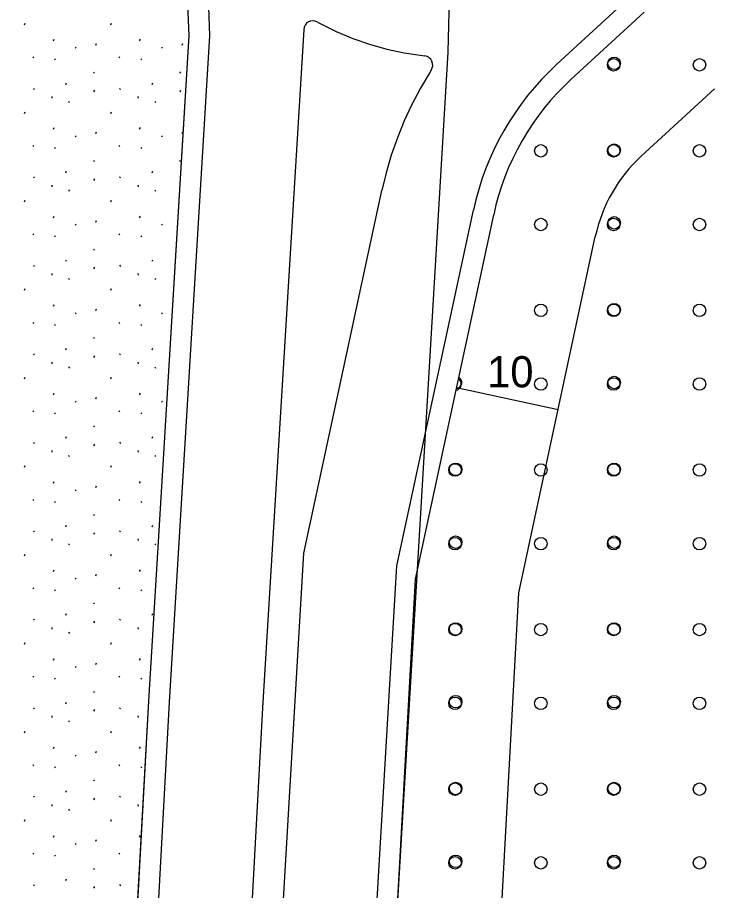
# Model space of a CAD drawing. Extents: x 419396 to 421519, y 4453567 to 4456767.
# Drawn here: x 420874 to 420941, y 4455563.3 to 4455647.3 of the extents above; entities that cross this region are included whole.
import ezdxf

# ---------------------------------------------------------------- set-up
doc = ezdxf.new("R2010")
doc.units = 0
for name, color, linetype in [('0_KADASTRO', 7, 'Continuous'), ('ADAKENARI1000', 7, 'Continuous'), ('F_YAPI_YAKLAŞMA', 7, 'Continuous'), ('KALDIRIM', 7, 'Continuous'), ('Level 33', 7, 'Continuous'), ('Level 41', 7, 'Continuous')]:
    doc.layers.add(name, color=color, linetype=linetype)

msp = doc.modelspace()

# ---------------------------------------------------------------- linework, layer by layer
at = {"layer": '0_KADASTRO'}
msp.add_lwpolyline([(420545.417, 4455447.038), (420561.035, 4455696.592), (420608.268, 4455685.53), (420614.844, 4455734.095), (420621.113, 4455745.073), (420621.38, 4455786.205), (420636.291, 4455823.285), (420701.58, 4455861.23), (420708.62, 4455863.92), (420715.79, 4455864.57), (420723.78, 4455862.78), (420730.13, 4455859.19), (420735, 4455853.4), (420771.9, 4455797.51), (420787.06, 4455778.4), (420884.04, 4455668.02), (420888.93, 4455658.72), (420890.16, 4455653.06), (420890.461, 4455645.521), (420886.579, 4455581.517), (420884.979, 4455552.191), (420718.56, 4455563.04), (420710.4, 4455437.34), (420549.3, 4455446.81)], close=True, dxfattribs=at)
msp.add_lwpolyline([(420889.849, 4455182.58), (420910.449, 4455560.119), (420915.412, 4455643.953), (420915.577, 4455650.455), (420914.598, 4455657.957), (420913.457, 4455663.665), (420911.337, 4455669.862), (420909.752, 4455673.126), (420911.566, 4455679.673), (420935.859, 4455688.268), (420947.761, 4455688.766), (420960.081, 4455684.751), (420973.092, 4455678.471), (421003.122, 4455663.97), (421028.474, 4455648.453), (421040.228, 4455638.432), (421137.175, 4455559.091), (421140.509, 4455550.953), (421136.038, 4455509.502), (421128.218, 4455437.471), (421062.987, 4455307.75)], dxfattribs=at)
at = {"layer": 'ADAKENARI1000'}
for p, q in [((420890.16, 4455653.06), (420890.46, 4455645.54)), ((420927.217, 4455641.299), (420934.264, 4455647.783)), ((420890.46, 4455645.54), (420886.579, 4455581.517)), ((420912.257, 4455593.26), (420919.791, 4455628.308)), ((420899.408, 4455357.777), (420912.257, 4455593.26)), ((420886.579, 4455581.517), (420884.979, 4455552.191))]:
    msp.add_line(p, q, dxfattribs=at)
msp.add_arc((420943.952, 4455623.115), 24.712, 132.62198, 167.86854, dxfattribs=at)
at = {"layer": 'F_YAPI_YAKLAŞMA'}
for p, q in [((420933.989, 4455633.941), (420941.035, 4455640.425)), ((420922.2, 4455591.928), (420929.568, 4455626.206)), ((420925.987, 4455609.549), (420916.211, 4455611.651)), ((420909.394, 4455357.232), (420922.2, 4455591.928))]:
    msp.add_line(p, q, dxfattribs=at)
msp.add_arc((420943.952, 4455623.115), 14.712, 132.62198, 167.86854, dxfattribs=at)
at = {"layer": 'KALDIRIM'}
for p, q in [((420892.153, 4455653.269), (420892.462, 4455645.519)), ((420925.863, 4455642.771), (420932.91, 4455649.255)), ((420901.516, 4455646.126), (420897.561, 4455580.885)), ((420902.836, 4455646.84), (420903.096, 4455646.691)), ((420903.096, 4455646.691), (420904.64, 4455645.931)), ((420892.462, 4455645.519), (420888.576, 4455581.402)), ((420904.64, 4455645.931), (420906.228, 4455645.268)), ((420906.228, 4455645.268), (420907.854, 4455644.704)), ((420907.854, 4455644.704), (420909.511, 4455644.241)), ((420909.511, 4455644.241), (420911.194, 4455643.88)), ((420911.194, 4455643.88), (420913.182, 4455643.58)), ((420913.641, 4455641.999), (420912.746, 4455640.481)), ((420913.788, 4455642.222), (420913.641, 4455641.999)), ((420912.746, 4455640.481), (420911.927, 4455638.92)), ((420911.927, 4455638.92), (420911.187, 4455637.321)), ((420911.187, 4455637.321), (420910.526, 4455635.688)), ((420910.526, 4455635.688), (420909.946, 4455634.024)), ((420909.946, 4455634.024), (420909.449, 4455632.333)), ((420909.449, 4455632.333), (420909.037, 4455630.62)), ((420901.538, 4455595.736), (420909.037, 4455630.62)), ((420910.482, 4455594.517), (420917.836, 4455628.728)), ((420899.467, 4455560.744), (420901.538, 4455595.736)), ((420908.452, 4455560.233), (420910.482, 4455594.517)), ((420888.576, 4455581.402), (420886.976, 4455552.082)), ((420897.561, 4455580.885), (420895.963, 4455551.592))]:
    msp.add_line(p, q, dxfattribs=at)
for centre, radius, start, end in [((420902.398, 4455646.072), 0.884, 60.28995, 176.53104), ((420913.05, 4455642.707), 0.882, 326.66214, 81.42048), ((420943.952, 4455623.115), 26.712, 132.62198, 167.86854)]:
    msp.add_arc(centre, radius, start, end, dxfattribs=at)
at = {"layer": 'Level 33'}
for centre in [(420931.332, 4455642.719), (420931.387, 4455642.87), (420939.589, 4455642.719), (420924.332, 4455634.455), (420931.332, 4455634.455), (420931.387, 4455634.518), (420939.589, 4455634.455), (420924.332, 4455627.367), (420931.332, 4455627.367), (420931.387, 4455627.518), (420939.589, 4455627.367), (420924.332, 4455619.103), (420931.332, 4455619.103), (420931.387, 4455619.166), (420939.589, 4455619.103), (420924.332, 4455612.015), (420931.332, 4455612.015), (420931.387, 4455612.166), (420939.589, 4455612.015), (420916.075, 4455603.751), (420916.13, 4455603.814), (420924.332, 4455603.751), (420931.332, 4455603.751), (420931.387, 4455603.814), (420939.589, 4455603.751), (420916.13, 4455596.814), (420931.387, 4455596.814), (420916.075, 4455596.663), (420924.332, 4455596.663), (420931.332, 4455596.663), (420939.589, 4455596.663), (420916.075, 4455588.399), (420916.13, 4455588.462), (420924.332, 4455588.399), (420931.332, 4455588.399), (420931.387, 4455588.462), (420939.589, 4455588.399), (420916.075, 4455581.311), (420916.13, 4455581.462), (420924.332, 4455581.311), (420931.332, 4455581.311), (420931.387, 4455581.462), (420939.589, 4455581.311), (420916.075, 4455573.047), (420916.13, 4455573.11), (420924.332, 4455573.047), (420931.332, 4455573.047), (420931.387, 4455573.11), (420939.589, 4455573.047), (420916.075, 4455565.959), (420916.13, 4455566.11), (420924.332, 4455565.959), (420931.332, 4455565.959), (420931.387, 4455566.11), (420939.589, 4455565.959)]:
    msp.add_circle(centre, 0.6, dxfattribs=at)
for centre, start, end in [((420916.075, 4455612.015), 278.29903, 57.43805), ((420916.13, 4455612.166), 276.0035, 59.73359)]:
    msp.add_arc(centre, 0.6, start, end, dxfattribs=at)
at = {"layer": 'Level 41'}
for p, q in [((420874.669, 4455646.561), (420874.741, 4455646.721)), ((420882.962, 4455646.561), (420883.034, 4455646.721)), ((420877.441, 4455645.031), (420877.511, 4455645.191)), ((420879.536, 4455644.415), (420879.607, 4455644.309)), ((420881.524, 4455644.623), (420881.595, 4455644.783)), ((420885.734, 4455645.031), (420885.804, 4455645.191)), ((420887.829, 4455644.415), (420887.9, 4455644.309)), ((420889.817, 4455644.623), (420889.888, 4455644.783)), ((420875.451, 4455643.486), (420875.522, 4455643.379)), ((420877.55, 4455643.294), (420877.621, 4455643.187)), ((420883.744, 4455643.486), (420883.815, 4455643.379)), ((420885.843, 4455643.294), (420885.914, 4455643.187)), ((420881.288, 4455642.033), (420881.359, 4455641.926)), ((420889.581, 4455642.033), (420889.652, 4455641.926)), ((420875.518, 4455640.456), (420875.589, 4455640.349)), ((420878.647, 4455640.84), (420878.718, 4455640.999)), ((420881.346, 4455640.111), (420881.418, 4455640.271)), ((420883.811, 4455640.456), (420883.882, 4455640.349)), ((420886.94, 4455640.84), (420887.011, 4455640.999)), ((420889.639, 4455640.111), (420889.711, 4455640.271)), ((420877.276, 4455639.665), (420877.294, 4455639.505)), ((420885.569, 4455639.665), (420885.587, 4455639.505)), ((420878.906, 4455639.195), (420878.976, 4455639.088)), ((420887.199, 4455639.195), (420887.269, 4455639.088)), ((420874.669, 4455638.051), (420874.741, 4455638.211)), ((420882.962, 4455638.051), (420883.034, 4455638.211)), ((420877.441, 4455636.521), (420877.511, 4455636.681)), ((420881.524, 4455636.113), (420881.595, 4455636.273)), ((420885.734, 4455636.521), (420885.804, 4455636.681)), ((420889.817, 4455636.113), (420889.888, 4455636.273)), ((420879.536, 4455635.905), (420879.607, 4455635.799)), ((420887.829, 4455635.905), (420887.9, 4455635.799)), ((420875.451, 4455634.976), (420875.522, 4455634.869)), ((420877.55, 4455634.784), (420877.621, 4455634.677)), ((420883.744, 4455634.976), (420883.815, 4455634.869)), ((420885.843, 4455634.784), (420885.914, 4455634.677)), ((420881.288, 4455633.523), (420881.359, 4455633.416)), ((420889.581, 4455633.523), (420889.652, 4455633.416)), ((420875.518, 4455631.946), (420875.589, 4455631.839)), ((420878.647, 4455632.33), (420878.718, 4455632.489)), ((420883.811, 4455631.946), (420883.882, 4455631.839)), ((420886.94, 4455632.33), (420887.011, 4455632.489)), ((420877.276, 4455631.155), (420877.294, 4455630.995)), ((420881.346, 4455631.601), (420881.418, 4455631.761)), ((420885.569, 4455631.155), (420885.587, 4455630.995)), ((420878.906, 4455630.685), (420878.976, 4455630.578)), ((420887.199, 4455630.685), (420887.269, 4455630.578)), ((420874.669, 4455629.541), (420874.741, 4455629.701)), ((420882.962, 4455629.541), (420883.034, 4455629.701)), ((420877.441, 4455628.011), (420877.511, 4455628.171)), ((420881.524, 4455627.603), (420881.595, 4455627.763)), ((420885.734, 4455628.011), (420885.804, 4455628.171)), ((420879.536, 4455627.395), (420879.607, 4455627.289)), ((420887.829, 4455627.395), (420887.9, 4455627.289)), ((420875.451, 4455626.466), (420875.522, 4455626.359)), ((420877.55, 4455626.274), (420877.621, 4455626.167)), ((420883.744, 4455626.466), (420883.815, 4455626.359)), ((420885.843, 4455626.274), (420885.914, 4455626.167)), ((420881.288, 4455625.013), (420881.359, 4455624.906)), ((420875.518, 4455623.436), (420875.589, 4455623.329)), ((420878.647, 4455623.82), (420878.718, 4455623.979)), ((420883.811, 4455623.436), (420883.882, 4455623.329)), ((420886.94, 4455623.82), (420887.011, 4455623.979)), ((420877.276, 4455622.645), (420877.294, 4455622.485)), ((420881.346, 4455623.091), (420881.418, 4455623.251)), ((420885.569, 4455622.645), (420885.587, 4455622.485)), ((420878.906, 4455622.175), (420878.976, 4455622.068)), ((420887.199, 4455622.175), (420887.269, 4455622.068)), ((420874.669, 4455621.031), (420874.741, 4455621.191)), ((420882.962, 4455621.031), (420883.034, 4455621.191)), ((420877.441, 4455619.501), (420877.511, 4455619.661)), ((420881.524, 4455619.093), (420881.595, 4455619.253)), ((420885.734, 4455619.501), (420885.804, 4455619.661)), ((420879.536, 4455618.885), (420879.607, 4455618.779)), ((420887.829, 4455618.885), (420887.9, 4455618.779)), ((420875.451, 4455617.956), (420875.522, 4455617.849)), ((420877.55, 4455617.764), (420877.621, 4455617.657)), ((420883.744, 4455617.956), (420883.815, 4455617.849)), ((420885.843, 4455617.764), (420885.914, 4455617.657)), ((420881.288, 4455616.503), (420881.359, 4455616.396)), ((420878.647, 4455615.31), (420878.718, 4455615.469)), ((420886.94, 4455615.31), (420887.011, 4455615.469)), ((420875.518, 4455614.926), (420875.589, 4455614.819)), ((420881.346, 4455614.581), (420881.418, 4455614.741)), ((420883.811, 4455614.926), (420883.882, 4455614.819)), ((420877.276, 4455614.135), (420877.294, 4455613.975)), ((420878.906, 4455613.665), (420878.976, 4455613.558)), ((420885.569, 4455614.135), (420885.587, 4455613.975)), ((420887.199, 4455613.665), (420887.269, 4455613.558)), ((420874.669, 4455612.521), (420874.741, 4455612.681)), ((420882.962, 4455612.521), (420883.034, 4455612.681)), ((420877.441, 4455610.991), (420877.511, 4455611.151)), ((420885.734, 4455610.991), (420885.804, 4455611.151)), ((420879.536, 4455610.375), (420879.607, 4455610.269)), ((420881.524, 4455610.583), (420881.595, 4455610.743)), ((420887.829, 4455610.375), (420887.9, 4455610.269)), ((420875.451, 4455609.446), (420875.522, 4455609.339)), ((420877.55, 4455609.254), (420877.621, 4455609.147)), ((420883.744, 4455609.446), (420883.815, 4455609.339)), ((420885.843, 4455609.254), (420885.914, 4455609.147)), ((420881.288, 4455607.993), (420881.359, 4455607.886)), ((420878.647, 4455606.8), (420878.718, 4455606.959)), ((420886.94, 4455606.8), (420887.011, 4455606.959)), ((420875.518, 4455606.416), (420875.589, 4455606.309)), ((420881.346, 4455606.071), (420881.418, 4455606.231)), ((420883.811, 4455606.416), (420883.882, 4455606.309)), ((420877.276, 4455605.625), (420877.294, 4455605.465)), ((420878.906, 4455605.155), (420878.976, 4455605.048)), ((420885.569, 4455605.625), (420885.587, 4455605.465)), ((420887.199, 4455605.155), (420887.269, 4455605.048)), ((420874.669, 4455604.011), (420874.741, 4455604.171)), ((420882.962, 4455604.011), (420883.034, 4455604.171)), ((420877.441, 4455602.481), (420877.511, 4455602.641)), ((420885.734, 4455602.481), (420885.804, 4455602.641)), ((420879.536, 4455601.865), (420879.607, 4455601.759)), ((420881.524, 4455602.073), (420881.595, 4455602.233)), ((420875.451, 4455600.936), (420875.522, 4455600.829)), ((420877.55, 4455600.744), (420877.621, 4455600.637)), ((420883.744, 4455600.936), (420883.815, 4455600.829)), ((420885.843, 4455600.744), (420885.914, 4455600.637)), ((420881.288, 4455599.483), (420881.359, 4455599.376)), ((420878.647, 4455598.29), (420878.718, 4455598.449)), ((420886.94, 4455598.29), (420887.011, 4455598.449)), ((420875.518, 4455597.906), (420875.589, 4455597.799)), ((420881.346, 4455597.561), (420881.418, 4455597.721)), ((420883.811, 4455597.906), (420883.882, 4455597.799)), ((420877.276, 4455597.115), (420877.294, 4455596.955)), ((420878.906, 4455596.645), (420878.976, 4455596.538)), ((420885.569, 4455597.115), (420885.587, 4455596.955)), ((420887.199, 4455596.645), (420887.269, 4455596.538)), ((420874.669, 4455595.501), (420874.741, 4455595.661)), ((420882.962, 4455595.501), (420883.034, 4455595.661)), ((420877.441, 4455593.971), (420877.511, 4455594.131)), ((420885.734, 4455593.971), (420885.804, 4455594.131)), ((420879.536, 4455593.355), (420879.607, 4455593.249)), ((420881.524, 4455593.563), (420881.595, 4455593.723)), ((420875.451, 4455592.426), (420875.522, 4455592.319)), ((420883.744, 4455592.426), (420883.815, 4455592.319)), ((420877.55, 4455592.234), (420877.621, 4455592.127)), ((420885.843, 4455592.234), (420885.914, 4455592.127)), ((420881.288, 4455590.973), (420881.359, 4455590.866)), ((420878.647, 4455589.78), (420878.718, 4455589.939)), ((420886.94, 4455589.78), (420887.011, 4455589.939)), ((420875.518, 4455589.396), (420875.589, 4455589.289)), ((420881.346, 4455589.051), (420881.418, 4455589.211)), ((420883.811, 4455589.396), (420883.882, 4455589.289)), ((420877.276, 4455588.605), (420877.294, 4455588.445)), ((420878.906, 4455588.135), (420878.976, 4455588.028)), ((420885.569, 4455588.605), (420885.587, 4455588.445)), ((420874.669, 4455586.991), (420874.741, 4455587.151)), ((420882.962, 4455586.991), (420883.034, 4455587.151)), ((420877.441, 4455585.461), (420877.511, 4455585.621)), ((420885.734, 4455585.461), (420885.804, 4455585.621)), ((420879.536, 4455584.845), (420879.607, 4455584.739)), ((420881.524, 4455585.053), (420881.595, 4455585.213)), ((420875.451, 4455583.916), (420875.522, 4455583.809)), ((420877.55, 4455583.724), (420877.621, 4455583.617)), ((420883.744, 4455583.916), (420883.815, 4455583.809)), ((420885.843, 4455583.724), (420885.914, 4455583.617)), ((420881.288, 4455582.463), (420881.359, 4455582.356)), ((420878.647, 4455581.27), (420878.718, 4455581.429)), ((420875.518, 4455580.886), (420875.589, 4455580.779)), ((420881.346, 4455580.541), (420881.418, 4455580.701)), ((420883.811, 4455580.886), (420883.882, 4455580.779)), ((420877.276, 4455580.095), (420877.294, 4455579.935)), ((420885.569, 4455580.095), (420885.587, 4455579.935)), ((420878.906, 4455579.625), (420878.976, 4455579.518)), ((420874.669, 4455578.481), (420874.741, 4455578.641)), ((420882.962, 4455578.481), (420883.034, 4455578.641)), ((420877.441, 4455576.951), (420877.511, 4455577.111)), ((420881.524, 4455576.543), (420881.595, 4455576.703)), ((420885.734, 4455576.951), (420885.804, 4455577.111)), ((420879.536, 4455576.335), (420879.607, 4455576.229)), ((420875.451, 4455575.406), (420875.522, 4455575.299)), ((420877.55, 4455575.214), (420877.621, 4455575.107)), ((420883.744, 4455575.406), (420883.815, 4455575.299)), ((420885.843, 4455575.214), (420885.914, 4455575.107)), ((420881.288, 4455573.953), (420881.359, 4455573.846)), ((420875.518, 4455572.376), (420875.589, 4455572.269)), ((420878.647, 4455572.76), (420878.718, 4455572.919)), ((420881.346, 4455572.031), (420881.418, 4455572.191)), ((420883.811, 4455572.376), (420883.882, 4455572.269)), ((420877.276, 4455571.585), (420877.294, 4455571.425)), ((420885.569, 4455571.585), (420885.587, 4455571.425)), ((420878.906, 4455571.115), (420878.976, 4455571.008)), ((420874.669, 4455569.971), (420874.741, 4455570.131)), ((420882.962, 4455569.971), (420883.034, 4455570.131)), ((420877.441, 4455568.441), (420877.511, 4455568.601)), ((420881.524, 4455568.033), (420881.595, 4455568.193)), ((420885.734, 4455568.441), (420885.804, 4455568.601)), ((420879.536, 4455567.825), (420879.607, 4455567.719)), ((420875.451, 4455566.896), (420875.522, 4455566.789)), ((420877.55, 4455566.704), (420877.621, 4455566.597)), ((420883.744, 4455566.896), (420883.815, 4455566.789)), ((420881.288, 4455565.443), (420881.359, 4455565.336)), ((420875.518, 4455563.866), (420875.589, 4455563.759)), ((420878.647, 4455564.25), (420878.718, 4455564.409)), ((420883.811, 4455563.866), (420883.882, 4455563.759)), ((420881.346, 4455563.521), (420881.418, 4455563.681))]:
    msp.add_line(p, q, dxfattribs=at)

# ---------------------------------------------------------------- texts
at = {"layer": 'F_YAPI_YAKLAŞMA'}
msp.add_text('10', height=3, dxfattribs=at).set_placement((420919.161, 4455611.701))

doc.saveas('drawing.dxf')
